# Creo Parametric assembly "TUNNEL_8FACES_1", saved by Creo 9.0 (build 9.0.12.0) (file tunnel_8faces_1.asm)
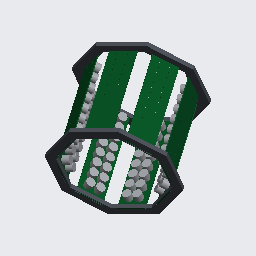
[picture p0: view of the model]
Units: millimeter Newton Second (mmNs); MM, TONNE, SECS

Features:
  1. coordinate system "TUNNEL_8FACES_1"
  2. imported feature "Import Feature id 4"
  3. component "PANEL_8F_01"
  4. component "PANEL_8F_02"
  5. component "PANEL_8F_03"
  6. component "PANEL_8F_04"
  7. component "PANEL_8F_05"
  8. component "PANEL_8F_06"
  9. component "PANEL_8F_07"
  10. component "PANEL_8F_08"
  11. component "RING_8F_LOWER"
  12. component "RING_8F_LOWER"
